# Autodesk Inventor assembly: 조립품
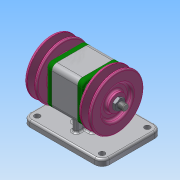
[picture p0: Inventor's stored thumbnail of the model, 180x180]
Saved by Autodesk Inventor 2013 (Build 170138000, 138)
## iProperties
Created: 2020-11
Part Number: 조립품
Document SubType Name: Assembly
Designer: user
Author: user
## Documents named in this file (10)
- C:\Users\user\Desktop\701106V1034\조립품.iam
- C:\Users\user\Desktop\701106V1034\본체.ipt
- C:\Users\user\Desktop\701106V1034\축.ipt
- C:\Users\user\Desktop\701106V1034\Ű 5 x 5 x 12.ipt
- C:\Users\user\Desktop\701106V1034\V-벨트풀리.ipt
- C:\Users\user\Desktop\701106V1034\너트 M10x1.ipt
- C:\Users\user\Desktop\701106V1034\베어링 6004.ipt
- C:\Users\user\Desktop\701106V1034\볼트 M4.ipt
- C:\Users\user\Desktop\701106V1034\오일 실 17 30 5.ipt
- C:\Users\user\Desktop\701106V1034\커버.ipt
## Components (4 placed, 2 different names)
1. Ű 5 x 5 x 12:1
2. V-벨트풀리:1
3. Ű 5 x 5 x 12:2 — 각도:1
4. V-벨트풀리:2
## Component patterns: 구성요소 패턴 1:2 (2 elements), 구성요소 패턴 3:2 (2 elements)
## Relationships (1: Angle 1)
- 각도:1 [Angle]: Ű 5 x 5 x 12:2
